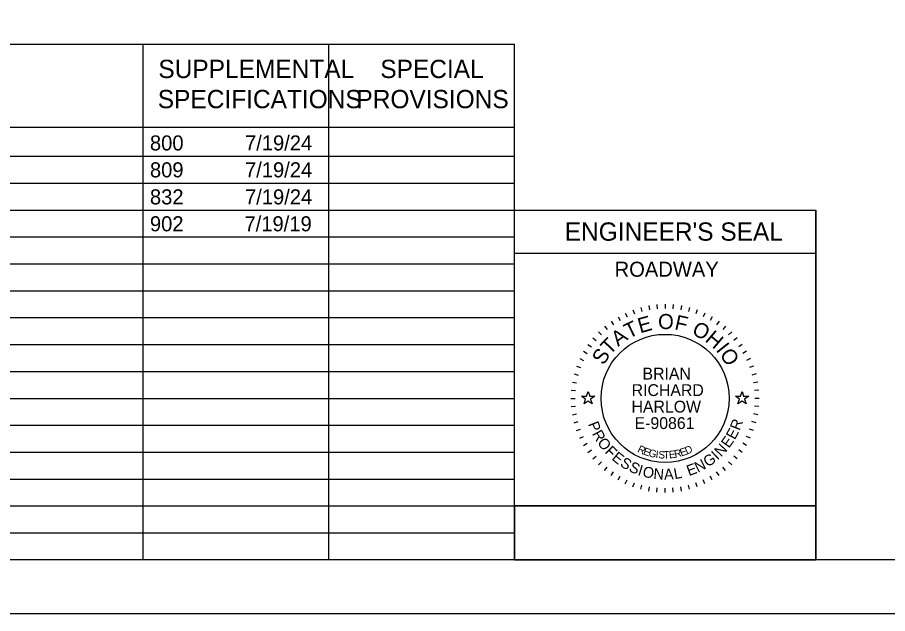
# Model space of a CAD drawing. Extents: x 0 to 34, y 0 to 22.
# Drawn here: x 20.08 to 28.17, y 0 to 5.54 of the extents above; entities that cross this region are included whole.
import ezdxf

# ---------------------------------------------------------------- set-up
doc = ezdxf.new("R2010")
doc.units = 0
for name, color, linetype in [('Default', 7, 'Continuous'), ('SH_Border', 7, 'Continuous'), ('SH_Cut_Line', 7, 'Continuous'), ('SH_Data', 7, 'Continuous'), ('SH_Text', 7, 'Continuous')]:
    doc.layers.add(name, color=color, linetype=linetype)

msp = doc.modelspace()

# ---------------------------------------------------------------- linework, layer by layer
at = {"layer": 'Default'}
for points in [[(25.3236, 2.02), (25.3705, 2.02), (25.385, 2.0645), (25.3995, 2.02), (25.4464, 2.02), (25.4085, 1.9924), (25.423, 1.9478), (25.385, 1.9754), (25.347, 1.9478), (25.3615, 1.9924)], [(26.7536, 2.02), (26.8005, 2.02), (26.815, 2.0645), (26.8295, 2.02), (26.8764, 2.02), (26.8385, 1.9924), (26.853, 1.9478), (26.815, 1.9754), (26.777, 1.9478), (26.7915, 1.9924)]]:
    msp.add_lwpolyline(points, close=True, dxfattribs=at)
at = {"layer": 'SH_Border'}
msp.add_lwpolyline([(1.5, 21.5), (33.5, 21.5), (33.5, 0.5), (1.5, 0.5)], close=True, dxfattribs=at)
at = {"layer": 'SH_Cut_Line'}
msp.add_lwpolyline([(0, 0), (34, 0), (34, 22), (0, 22)], close=True, dxfattribs=at)
at = {"layer": 'SH_Data'}
for p, q in [((11.25, 5.2917), (24.7, 5.2917)), ((21.25, 0.5), (21.25, 5.2917)), ((22.975, 0.5), (22.975, 5.2917)), ((24.7, 0.5), (24.7, 5.2917)), ((11.25, 4.5209), (24.7, 4.5209)), ((11.25, 4.25), (24.7, 4.25)), ((11.25, 4), (24.7, 4)), ((11.25, 3.75), (24.7, 3.75)), ((24.7, 0.5), (24.7, 3.75)), ((24.7, 3.75), (27.5, 3.75)), ((27.5, 0.5), (27.5, 3.75)), ((27.5, 3.75), (27.5, 0.5)), ((11.25, 3.5), (24.7, 3.5)), ((24.7, 3.35), (27.5, 3.35)), ((11.25, 3.25), (24.7, 3.25)), ((11.25, 3), (24.7, 3)), ((25.8735, 2.8452), (25.8839, 2.8065)), ((25.9481, 2.8617), (25.955, 2.8223)), ((26.0237, 2.8717), (26.0272, 2.8318)), ((26.1, 2.875), (26.1, 2.835)), ((26.1763, 2.8717), (26.1728, 2.8318)), ((26.2519, 2.8617), (26.245, 2.8223)), ((26.3265, 2.8452), (26.3161, 2.8065)), ((11.25, 2.75), (24.7, 2.75)), ((25.6625, 2.7578), (25.6825, 2.7231)), ((25.7302, 2.793), (25.7471, 2.7568)), ((25.8007, 2.8222), (25.8144, 2.7846)), ((26.3993, 2.8222), (26.3856, 2.7846)), ((26.4698, 2.793), (26.4529, 2.7568)), ((26.5375, 2.7578), (26.5175, 2.7231)), ((25.5376, 2.6703), (25.5633, 2.6396)), ((25.5981, 2.7168), (25.6211, 2.684)), ((26.6019, 2.7168), (26.5789, 2.684)), ((26.6624, 2.6703), (26.6367, 2.6396)), ((25.4813, 2.6187), (25.5096, 2.5904)), ((26.7187, 2.6187), (26.6904, 2.5904)), ((25.4297, 2.5624), (25.4604, 2.5367)), ((26.7703, 2.5624), (26.7396, 2.5367)), ((11.25, 2.5), (24.7, 2.5)), ((25.3422, 2.4375), (25.3769, 2.4175)), ((25.3832, 2.5019), (25.416, 2.4789)), ((26.8168, 2.5019), (26.784, 2.4789)), ((26.8578, 2.4375), (26.8231, 2.4175)), ((25.307, 2.3698), (25.3432, 2.3529)), ((26.893, 2.3698), (26.8568, 2.3529)), ((25.2778, 2.2993), (25.3154, 2.2856)), ((26.9222, 2.2993), (26.8846, 2.2856)), ((11.25, 2.25), (24.7, 2.25)), ((25.2548, 2.2265), (25.2935, 2.2161)), ((26.9452, 2.2265), (26.9065, 2.2161)), ((25.2383, 2.1519), (25.2777, 2.145)), ((26.9617, 2.1519), (26.9223, 2.145)), ((25.2283, 2.0763), (25.2682, 2.0728)), ((26.9717, 2.0763), (26.9318, 2.0728)), ((11.25, 2), (24.7, 2)), ((25.225, 2), (25.265, 2)), ((26.975, 2), (26.935, 2)), ((25.2283, 1.9237), (25.2682, 1.9272)), ((26.9717, 1.9237), (26.9318, 1.9272)), ((25.2383, 1.8481), (25.2777, 1.855)), ((25.2548, 1.7735), (25.2935, 1.7839)), ((26.9452, 1.7735), (26.9065, 1.7839)), ((26.9617, 1.8481), (26.9223, 1.855)), ((11.25, 1.75), (24.7, 1.75)), ((25.2778, 1.7007), (25.3154, 1.7144)), ((26.9222, 1.7007), (26.8846, 1.7144)), ((25.307, 1.6302), (25.3432, 1.6471)), ((26.893, 1.6302), (26.8568, 1.6471)), ((25.3422, 1.5625), (25.3769, 1.5825)), ((26.8578, 1.5625), (26.8231, 1.5825)), ((11.25, 1.5), (24.7, 1.5)), ((25.3832, 1.4981), (25.416, 1.5211)), ((25.4297, 1.4376), (25.4604, 1.4633)), ((26.7703, 1.4376), (26.7396, 1.4633)), ((26.8168, 1.4981), (26.784, 1.5211)), ((25.4813, 1.3813), (25.5096, 1.4096)), ((26.7187, 1.3813), (26.6904, 1.4096)), ((25.5376, 1.3297), (25.5633, 1.3604)), ((25.5981, 1.2832), (25.6211, 1.316)), ((26.6019, 1.2832), (26.5789, 1.316)), ((26.6624, 1.3297), (26.6367, 1.3604)), ((11.25, 1.25), (24.7, 1.25)), ((25.6625, 1.2422), (25.6825, 1.2769)), ((25.7302, 1.207), (25.7471, 1.2432)), ((25.8007, 1.1778), (25.8144, 1.2154)), ((26.3993, 1.1778), (26.3856, 1.2154)), ((26.4698, 1.207), (26.4529, 1.2432)), ((26.5375, 1.2422), (26.5175, 1.2769)), ((25.8735, 1.1548), (25.8839, 1.1935)), ((25.9481, 1.1383), (25.955, 1.1777)), ((26.0237, 1.1283), (26.0272, 1.1682)), ((26.1, 1.125), (26.1, 1.165)), ((26.1763, 1.1283), (26.1728, 1.1682)), ((26.2519, 1.1383), (26.245, 1.1777)), ((26.3265, 1.1548), (26.3161, 1.1935)), ((11.25, 1), (24.7, 1)), ((11.25, 0.75), (24.7, 0.75)), ((27.5, 0.5), (24.7, 0.5)), ((24.7, 0.5), (27.5, 0.5))]:
    msp.add_line(p, q, dxfattribs=at)
for points in [[(27.5, 0.5), (27.5, 1), (24.7, 1), (24.7, 0.5)], [(24.7, 0.5), (24.7, 1), (27.5, 1), (27.5, 0.5)]]:
    msp.add_lwpolyline(points, close=True, dxfattribs=at)
msp.add_circle((26.1, 2), 0.595, dxfattribs=at)

# ---------------------------------------------------------------- texts
for s, height, p in [("ENGINEER'S SEAL", 0.17, (25.1676, 3.465)), ('ROADWAY', 0.14, (25.6311, 3.13)), ('BRIAN', 0.11, (25.8902, 2.1749)), ('RICHARD', 0.11, (25.7895, 2.0216)), ('HARLOW', 0.11, (25.788, 1.8684)), ('E-90861', 0.11, (25.8167, 1.7151))]:
    msp.add_text(s, height=height, dxfattribs=at).set_placement(p)
for s, height, rotation, p in [('E', 0.14, 15.75706, (25.8684, 2.6038)), ('O', 0.14, 359.78119, (26.0347, 2.6443)), ('F', 0.14, 347.43619, (26.1811, 2.6417)), ('T', 0.14, 25.71674, (25.7616, 2.5518)), ('O', 0.14, 332.25863, (26.3398, 2.6015)), ('A', 0.14, 36.47472, (25.6634, 2.4781)), ('H', 0.14, 319.91363, (26.4632, 2.5361)), ('T', 0.14, 46.4344, (25.5883, 2.3964)), ('I', 0.14, 308.36695, (26.5665, 2.4483)), ('S', 0.14, 57.19238, (25.5281, 2.3014)), ('O', 0.14, 303.14906, (26.6021, 2.4089)), ('P', 0.1, 291.49398, (25.3823, 1.7621)), ('R', 0.1, 69.23216, (26.7919, 1.6954)), ('R', 0.1, 298.73106, (25.419, 1.6717)), ('E', 0.1, 61.99508, (26.7476, 1.6098)), ('O', 0.1, 306.46664, (25.4655, 1.5883)), ('E', 0.1, 54.75801, (26.6933, 1.5314)), ('F', 0.1, 314.7068, (25.5343, 1.4983)), ('R', 0.07, 334.48695, (25.8375, 1.5051)), ('E', 0.07, 341.03996, (25.8906, 1.4801)), ('E', 0.07, 17.68363, (26.2498, 1.4602)), ('D', 0.07, 23.30524, (26.301, 1.477)), ('N', 0.1, 47.02243, (26.6202, 1.4508)), ('E', 0.1, 321.43929, (25.5978, 1.4348)), ('G', 0.07, 347.47515, (25.9414, 1.4618)), ('I', 0.07, 353.78581, (26.0091, 1.4468)), ('S', 0.07, 356.89262, (26.0358, 1.4429)), ('T', 0.07, 3.00609, (26.0857, 1.4387)), ('E', 0.07, 6.01169, (26.1389, 1.4412)), ('R', 0.07, 11.91844, (26.1925, 1.4474)), ('G', 0.1, 35.04687, (26.4981, 1.357)), ('I', 0.1, 43.28703, (26.5868, 1.4214)), ('S', 0.1, 328.67637, (25.6743, 1.3752)), ('S', 0.1, 335.91345, (25.7564, 1.3266)), ('I', 0.1, 343.15053, (25.8406, 1.2897)), ('E', 0.1, 20.07421, (26.3212, 1.277)), ('N', 0.1, 27.31129, (26.4045, 1.3075)), ('O', 0.1, 346.88592, (25.8839, 1.2751)), ('N', 0.1, 355.12608, (25.9888, 1.2517)), ('A', 0.1, 2.86166, (26.0923, 1.2437)), ('L', 0.1, 10.09874, (26.1894, 1.249))]:
    msp.add_text(s, height=height, rotation=rotation, dxfattribs=at).set_placement(p)
at = {"layer": 'SH_Text'}
for s, height, p in [('SUPPLEMENTAL', 0.17, (21.3925, 4.9763)), ('SPECIAL', 0.17, (23.4542, 4.9763)), ('SPECIFICATIONS', 0.17, (21.3871, 4.6963)), ('PROVISIONS', 0.17, (23.2323, 4.6963)), ('7/19/24', 0.14, (22.1973, 4.3036)), ('800', 0.14, (21.3141, 4.3036)), ('809', 0.14, (21.3141, 4.0536)), ('7/19/24', 0.14, (22.1973, 4.0536)), ('832', 0.14, (21.3141, 3.8022)), ('7/19/24', 0.14, (22.1973, 3.8022)), ('902', 0.14, (21.3141, 3.5522)), ('7/19/19', 0.14, (22.1926, 3.5522))]:
    msp.add_text(s, height=height, dxfattribs=at).set_placement(p)

doc.saveas('drawing.dxf')
